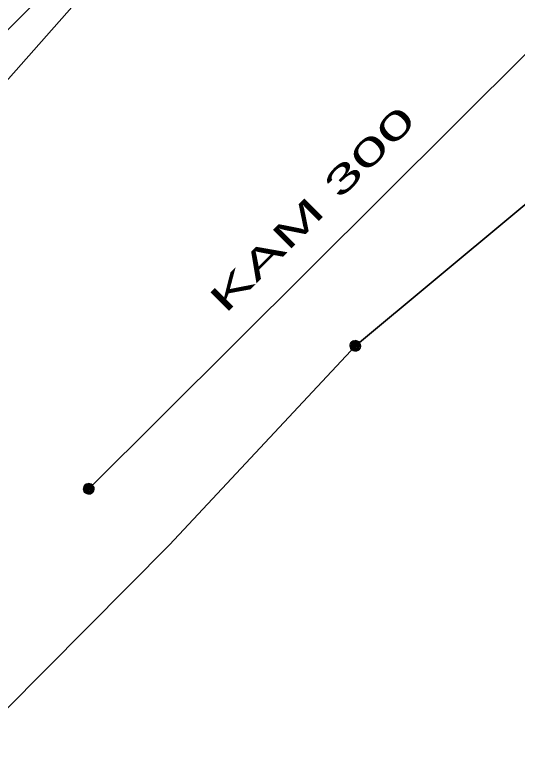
# Model space of a CAD drawing. Extents: x -867104 to -866746, y -1014489 to -1014255.
# Drawn here: x -866843.66 to -866822.42, y -1014431.21 to -1014399.43 of the extents above; entities that cross this region are included whole.
import ezdxf

# ---------------------------------------------------------------- set-up
doc = ezdxf.new("R2010")
doc.units = 0
doc.header["$LTSCALE"] = 0.44
for name, color, linetype, lineweight in [('1', 7, 'Continuous', 35), ('10', 7, 'Continuous', 13), ('12', 7, 'Continuous', 13), ('21', 7, 'Continuous', 35), ('34', 7, 'Continuous', 13)]:
    doc.layers.add(name, color=color, linetype=linetype, lineweight=lineweight)

msp = doc.modelspace()

# ---------------------------------------------------------------- linework, layer by layer
at = {"layer": '1'}
for points in [[(-866752.928, -1014345.35), (-866767.662, -1014356.784), (-866772.99, -1014363.51), (-866782.36, -1014374.33), (-866829.29, -1014413.39)], [(-866840.01, -1014396.11), (-866844.69, -1014400.78), (-866847.06, -1014402.96), (-866848.88, -1014406.15), (-866860.28, -1014424.67), (-866871.77, -1014440.29), (-866875.11, -1014444.27), (-866876.93, -1014446.09), (-866879, -1014449.37), (-866879.17, -1014450.73), (-866879.17, -1014451.68), (-866879.03, -1014452.53), (-866876.52, -1014455.41), (-866874.72, -1014458.69), (-866874.8, -1014459.33), (-866875.66, -1014460.47), (-866876.85, -1014461.77), (-866877.992, -1014463.135), (-866881.12, -1014466.73), (-866885.53, -1014471.37), (-866892.467, -1014476.423)], [(-866829.29, -1014413.39), (-866837.14, -1014421.79), (-866844.09, -1014428.8), (-866855.26, -1014440.32), (-866867.329, -1014452.641), (-866873.974, -1014459.295), (-866875.079, -1014460.444), (-866876.617, -1014462.044), (-866877.133, -1014462.581), (-866877.679, -1014463.149)]]:
    msp.add_lwpolyline(points, dxfattribs=at)
at = {"layer": '10'}
for points in [[(-866829.059, -1014413.39), (-866829.065, -1014413.338), (-866829.082, -1014413.288), (-866829.111, -1014413.244), (-866829.148, -1014413.207), (-866829.193, -1014413.18), (-866829.243, -1014413.163), (-866829.296, -1014413.159), (-866829.348, -1014413.166), (-866829.397, -1014413.185), (-866829.44, -1014413.214), (-866829.476, -1014413.253), (-866829.502, -1014413.298), (-866829.518, -1014413.349), (-866829.521, -1014413.401), (-866829.513, -1014413.453), (-866829.493, -1014413.502), (-866829.462, -1014413.545), (-866829.423, -1014413.579), (-866829.377, -1014413.605), (-866829.326, -1014413.619), (-866829.273, -1014413.621), (-866829.222, -1014413.611), (-866829.174, -1014413.59), (-866829.131, -1014413.559), (-866829.097, -1014413.518), (-866829.073, -1014413.472), (-866829.061, -1014413.421)], [(-866829.089, -1014413.39), (-866829.095, -1014413.341), (-866829.112, -1014413.295), (-866829.14, -1014413.255), (-866829.177, -1014413.223), (-866829.221, -1014413.201), (-866829.269, -1014413.19), (-866829.318, -1014413.19), (-866829.365, -1014413.203), (-866829.408, -1014413.227), (-866829.444, -1014413.26), (-866829.471, -1014413.301), (-866829.487, -1014413.348), (-866829.491, -1014413.397), (-866829.484, -1014413.445), (-866829.465, -1014413.49), (-866829.435, -1014413.53), (-866829.397, -1014413.561), (-866829.353, -1014413.581), (-866829.305, -1014413.591), (-866829.256, -1014413.589), (-866829.209, -1014413.574), (-866829.166, -1014413.549), (-866829.132, -1014413.515), (-866829.106, -1014413.473), (-866829.092, -1014413.426)], [(-866829.119, -1014413.39), (-866829.125, -1014413.345), (-866829.142, -1014413.303), (-866829.17, -1014413.268), (-866829.206, -1014413.241), (-866829.248, -1014413.224), (-866829.293, -1014413.219), (-866829.338, -1014413.225), (-866829.379, -1014413.244), (-866829.414, -1014413.272), (-866829.441, -1014413.309), (-866829.457, -1014413.351), (-866829.461, -1014413.396), (-866829.454, -1014413.441), (-866829.435, -1014413.482), (-866829.406, -1014413.516), (-866829.369, -1014413.542), (-866829.326, -1014413.558), (-866829.281, -1014413.561), (-866829.236, -1014413.553), (-866829.196, -1014413.533), (-866829.162, -1014413.504), (-866829.136, -1014413.466), (-866829.122, -1014413.423)], [(-866829.149, -1014413.39), (-866829.154, -1014413.349), (-866829.172, -1014413.312), (-866829.199, -1014413.281), (-866829.234, -1014413.26), (-866829.274, -1014413.249), (-866829.315, -1014413.251), (-866829.354, -1014413.264), (-866829.388, -1014413.288), (-866829.413, -1014413.32), (-866829.428, -1014413.358), (-866829.431, -1014413.399), (-866829.423, -1014413.439), (-866829.403, -1014413.475), (-866829.374, -1014413.504), (-866829.337, -1014413.523), (-866829.297, -1014413.531), (-866829.256, -1014413.527), (-866829.218, -1014413.512), (-866829.186, -1014413.486), (-866829.163, -1014413.452), (-866829.15, -1014413.413)], [(-866829.179, -1014413.39), (-866829.184, -1014413.354), (-866829.202, -1014413.322), (-866829.228, -1014413.297), (-866829.262, -1014413.282), (-866829.298, -1014413.279), (-866829.333, -1014413.287), (-866829.364, -1014413.307), (-866829.387, -1014413.335), (-866829.4, -1014413.369), (-866829.4, -1014413.406), (-866829.389, -1014413.441), (-866829.368, -1014413.47), (-866829.338, -1014413.491), (-866829.303, -1014413.501), (-866829.266, -1014413.499), (-866829.232, -1014413.485), (-866829.205, -1014413.462), (-866829.186, -1014413.43), (-866829.179, -1014413.395)], [(-866829.209, -1014413.39), (-866829.214, -1014413.359), (-866829.231, -1014413.333), (-866829.257, -1014413.316), (-866829.287, -1014413.309), (-866829.318, -1014413.313), (-866829.345, -1014413.33), (-866829.363, -1014413.354), (-866829.371, -1014413.385), (-866829.367, -1014413.415), (-866829.352, -1014413.443), (-866829.328, -1014413.462), (-866829.298, -1014413.471), (-866829.267, -1014413.468), (-866829.239, -1014413.454), (-866829.219, -1014413.43), (-866829.209, -1014413.401)], [(-866829.239, -1014413.39), (-866829.244, -1014413.366), (-866829.261, -1014413.348), (-866829.284, -1014413.339), (-866829.308, -1014413.342), (-866829.329, -1014413.356), (-866829.34, -1014413.378), (-866829.34, -1014413.403), (-866829.328, -1014413.424), (-866829.308, -1014413.438), (-866829.283, -1014413.441), (-866829.26, -1014413.432), (-866829.244, -1014413.414)], [(-866829.269, -1014413.39), (-866829.274, -1014413.375), (-866829.289, -1014413.369), (-866829.304, -1014413.373), (-866829.311, -1014413.387), (-866829.307, -1014413.402), (-866829.294, -1014413.411), (-866829.279, -1014413.408), (-866829.269, -1014413.396)]]:
    msp.add_lwpolyline(points, close=True, dxfattribs=at)
at = {"layer": '12'}
for points in [[(-866829.059, -1014413.39), (-866829.065, -1014413.338), (-866829.082, -1014413.288), (-866829.111, -1014413.244), (-866829.148, -1014413.207), (-866829.193, -1014413.18), (-866829.243, -1014413.163), (-866829.296, -1014413.159), (-866829.348, -1014413.166), (-866829.397, -1014413.185), (-866829.44, -1014413.214), (-866829.476, -1014413.253), (-866829.502, -1014413.298), (-866829.518, -1014413.349), (-866829.521, -1014413.401), (-866829.513, -1014413.453), (-866829.493, -1014413.502), (-866829.462, -1014413.545), (-866829.423, -1014413.579), (-866829.377, -1014413.605), (-866829.326, -1014413.619), (-866829.273, -1014413.621), (-866829.222, -1014413.611), (-866829.174, -1014413.59), (-866829.131, -1014413.559), (-866829.097, -1014413.518), (-866829.073, -1014413.472), (-866829.061, -1014413.421)], [(-866829.089, -1014413.39), (-866829.095, -1014413.341), (-866829.112, -1014413.295), (-866829.14, -1014413.255), (-866829.177, -1014413.223), (-866829.221, -1014413.201), (-866829.269, -1014413.19), (-866829.318, -1014413.19), (-866829.365, -1014413.203), (-866829.408, -1014413.227), (-866829.444, -1014413.26), (-866829.471, -1014413.301), (-866829.487, -1014413.348), (-866829.491, -1014413.397), (-866829.484, -1014413.445), (-866829.465, -1014413.49), (-866829.435, -1014413.53), (-866829.397, -1014413.561), (-866829.353, -1014413.581), (-866829.305, -1014413.591), (-866829.256, -1014413.589), (-866829.209, -1014413.574), (-866829.166, -1014413.549), (-866829.132, -1014413.515), (-866829.106, -1014413.473), (-866829.092, -1014413.426)], [(-866829.119, -1014413.39), (-866829.125, -1014413.345), (-866829.142, -1014413.303), (-866829.17, -1014413.268), (-866829.206, -1014413.241), (-866829.248, -1014413.224), (-866829.293, -1014413.219), (-866829.338, -1014413.225), (-866829.379, -1014413.244), (-866829.414, -1014413.272), (-866829.441, -1014413.309), (-866829.457, -1014413.351), (-866829.461, -1014413.396), (-866829.454, -1014413.441), (-866829.435, -1014413.482), (-866829.406, -1014413.516), (-866829.369, -1014413.542), (-866829.326, -1014413.558), (-866829.281, -1014413.561), (-866829.236, -1014413.553), (-866829.196, -1014413.533), (-866829.162, -1014413.504), (-866829.136, -1014413.466), (-866829.122, -1014413.423)], [(-866829.149, -1014413.39), (-866829.154, -1014413.349), (-866829.172, -1014413.312), (-866829.199, -1014413.281), (-866829.234, -1014413.26), (-866829.274, -1014413.249), (-866829.315, -1014413.251), (-866829.354, -1014413.264), (-866829.388, -1014413.288), (-866829.413, -1014413.32), (-866829.428, -1014413.358), (-866829.431, -1014413.399), (-866829.423, -1014413.439), (-866829.403, -1014413.475), (-866829.374, -1014413.504), (-866829.337, -1014413.523), (-866829.297, -1014413.531), (-866829.256, -1014413.527), (-866829.218, -1014413.512), (-866829.186, -1014413.486), (-866829.163, -1014413.452), (-866829.15, -1014413.413)], [(-866829.179, -1014413.39), (-866829.184, -1014413.354), (-866829.202, -1014413.322), (-866829.228, -1014413.297), (-866829.262, -1014413.282), (-866829.298, -1014413.279), (-866829.333, -1014413.287), (-866829.364, -1014413.307), (-866829.387, -1014413.335), (-866829.4, -1014413.369), (-866829.4, -1014413.406), (-866829.389, -1014413.441), (-866829.368, -1014413.47), (-866829.338, -1014413.491), (-866829.303, -1014413.501), (-866829.266, -1014413.499), (-866829.232, -1014413.485), (-866829.205, -1014413.462), (-866829.186, -1014413.43), (-866829.179, -1014413.395)], [(-866829.209, -1014413.39), (-866829.214, -1014413.359), (-866829.231, -1014413.333), (-866829.257, -1014413.316), (-866829.287, -1014413.309), (-866829.318, -1014413.313), (-866829.345, -1014413.33), (-866829.363, -1014413.354), (-866829.371, -1014413.385), (-866829.367, -1014413.415), (-866829.352, -1014413.443), (-866829.328, -1014413.462), (-866829.298, -1014413.471), (-866829.267, -1014413.468), (-866829.239, -1014413.454), (-866829.219, -1014413.43), (-866829.209, -1014413.401)], [(-866829.239, -1014413.39), (-866829.244, -1014413.366), (-866829.261, -1014413.348), (-866829.284, -1014413.339), (-866829.308, -1014413.342), (-866829.329, -1014413.356), (-866829.34, -1014413.378), (-866829.34, -1014413.403), (-866829.328, -1014413.424), (-866829.308, -1014413.438), (-866829.283, -1014413.441), (-866829.26, -1014413.432), (-866829.244, -1014413.414)], [(-866829.269, -1014413.39), (-866829.274, -1014413.375), (-866829.289, -1014413.369), (-866829.304, -1014413.373), (-866829.311, -1014413.387), (-866829.307, -1014413.402), (-866829.294, -1014413.411), (-866829.279, -1014413.408), (-866829.269, -1014413.396)]]:
    msp.add_lwpolyline(points, close=True, dxfattribs=at)
at = {"layer": '21'}
msp.add_line((-866821.947, -1014400.93), (-866840.548, -1014419.425), dxfattribs=at)
msp.add_lwpolyline([(-866846.197, -1014404.673), (-866828.183, -1014384.303), (-866770.762, -1014326.42)], dxfattribs=at)
at = {"layer": '34'}
for points in [[(-866840.316, -1014419.425), (-866840.323, -1014419.373), (-866840.34, -1014419.323), (-866840.369, -1014419.279), (-866840.406, -1014419.242), (-866840.451, -1014419.215), (-866840.5, -1014419.198), (-866840.554, -1014419.194), (-866840.605, -1014419.201), (-866840.654, -1014419.22), (-866840.698, -1014419.249), (-866840.733, -1014419.288), (-866840.76, -1014419.333), (-866840.776, -1014419.384), (-866840.779, -1014419.436), (-866840.771, -1014419.488), (-866840.75, -1014419.537), (-866840.72, -1014419.58), (-866840.681, -1014419.614), (-866840.635, -1014419.64), (-866840.583, -1014419.654), (-866840.531, -1014419.656), (-866840.48, -1014419.646), (-866840.431, -1014419.625), (-866840.389, -1014419.594), (-866840.355, -1014419.553), (-866840.331, -1014419.507), (-866840.318, -1014419.456)], [(-866840.347, -1014419.425), (-866840.353, -1014419.376), (-866840.37, -1014419.33), (-866840.397, -1014419.29), (-866840.434, -1014419.258), (-866840.478, -1014419.236), (-866840.527, -1014419.225), (-866840.576, -1014419.225), (-866840.622, -1014419.238), (-866840.666, -1014419.262), (-866840.701, -1014419.295), (-866840.728, -1014419.336), (-866840.745, -1014419.383), (-866840.749, -1014419.432), (-866840.742, -1014419.48), (-866840.723, -1014419.525), (-866840.693, -1014419.565), (-866840.654, -1014419.596), (-866840.61, -1014419.616), (-866840.563, -1014419.626), (-866840.514, -1014419.624), (-866840.467, -1014419.609), (-866840.424, -1014419.584), (-866840.389, -1014419.55), (-866840.364, -1014419.508), (-866840.35, -1014419.461)], [(-866840.377, -1014419.425), (-866840.382, -1014419.38), (-866840.399, -1014419.338), (-866840.428, -1014419.303), (-866840.463, -1014419.276), (-866840.505, -1014419.259), (-866840.551, -1014419.254), (-866840.595, -1014419.26), (-866840.637, -1014419.279), (-866840.671, -1014419.307), (-866840.698, -1014419.344), (-866840.715, -1014419.386), (-866840.718, -1014419.431), (-866840.712, -1014419.476), (-866840.693, -1014419.517), (-866840.664, -1014419.551), (-866840.627, -1014419.577), (-866840.583, -1014419.593), (-866840.539, -1014419.596), (-866840.494, -1014419.588), (-866840.453, -1014419.568), (-866840.419, -1014419.539), (-866840.394, -1014419.501), (-866840.38, -1014419.458)], [(-866840.407, -1014419.425), (-866840.411, -1014419.384), (-866840.429, -1014419.347), (-866840.456, -1014419.316), (-866840.492, -1014419.295), (-866840.532, -1014419.284), (-866840.573, -1014419.286), (-866840.612, -1014419.299), (-866840.646, -1014419.323), (-866840.671, -1014419.355), (-866840.686, -1014419.393), (-866840.688, -1014419.434), (-866840.681, -1014419.474), (-866840.661, -1014419.51), (-866840.632, -1014419.539), (-866840.595, -1014419.558), (-866840.554, -1014419.566), (-866840.514, -1014419.562), (-866840.475, -1014419.547), (-866840.443, -1014419.521), (-866840.421, -1014419.487), (-866840.407, -1014419.448)], [(-866840.436, -1014419.425), (-866840.441, -1014419.389), (-866840.46, -1014419.357), (-866840.485, -1014419.332), (-866840.519, -1014419.317), (-866840.556, -1014419.314), (-866840.59, -1014419.322), (-866840.622, -1014419.342), (-866840.644, -1014419.37), (-866840.657, -1014419.404), (-866840.657, -1014419.441), (-866840.647, -1014419.476), (-866840.625, -1014419.505), (-866840.595, -1014419.526), (-866840.561, -1014419.536), (-866840.524, -1014419.534), (-866840.49, -1014419.52), (-866840.463, -1014419.497), (-866840.443, -1014419.465), (-866840.436, -1014419.43)], [(-866840.467, -1014419.425), (-866840.472, -1014419.394), (-866840.489, -1014419.368), (-866840.514, -1014419.351), (-866840.544, -1014419.344), (-866840.576, -1014419.348), (-866840.603, -1014419.365), (-866840.62, -1014419.389), (-866840.629, -1014419.42), (-866840.625, -1014419.45), (-866840.61, -1014419.478), (-866840.585, -1014419.497), (-866840.556, -1014419.506), (-866840.524, -1014419.503), (-866840.497, -1014419.489), (-866840.477, -1014419.465), (-866840.467, -1014419.436)], [(-866840.497, -1014419.425), (-866840.502, -1014419.401), (-866840.519, -1014419.383), (-866840.541, -1014419.374), (-866840.566, -1014419.377), (-866840.587, -1014419.391), (-866840.598, -1014419.413), (-866840.598, -1014419.438), (-866840.585, -1014419.459), (-866840.566, -1014419.473), (-866840.541, -1014419.476), (-866840.517, -1014419.467), (-866840.502, -1014419.449)], [(-866840.527, -1014419.425), (-866840.532, -1014419.41), (-866840.546, -1014419.404), (-866840.561, -1014419.408), (-866840.568, -1014419.422), (-866840.565, -1014419.437), (-866840.551, -1014419.446), (-866840.536, -1014419.443), (-866840.527, -1014419.431)]]:
    msp.add_lwpolyline(points, close=True, dxfattribs=at)

# ---------------------------------------------------------------- texts
at = {"layer": '1', "width": 1.9}
msp.add_text('KAM 300 ', height=1.1, rotation=45, dxfattribs=at).set_placement((-866834.788, -1014412.076))

doc.saveas('drawing.dxf')
